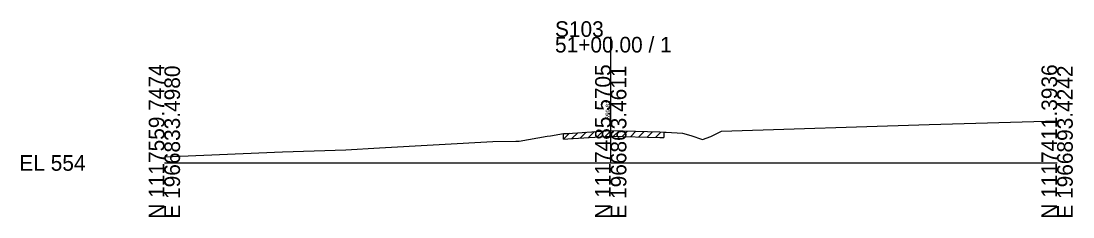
# Model space of a CAD drawing. Extents: x -26 to 163, y -10 to 24018.
# Drawn here: x -25.7 to 162.8, y 490.3 to 525.5 of the extents above; entities that cross this region are included whole.
import ezdxf

# ---------------------------------------------------------------- set-up
doc = ezdxf.new("R2010")
doc.units = 0
for name, color, linetype in [('RD_GPK_XS_Cell', 7, 'Continuous'), ('RD_XS_ExGround', 7, 'Continuous'), ('RD_XS_ExPaveRet', 7, 'Continuous'), ('RD_XS_TX_Elev_EX', 7, 'Continuous')]:
    doc.layers.add(name, color=color, linetype=linetype)

msp = doc.modelspace()

# ---------------------------------------------------------------- linework, layer by layer
at = {"layer": 'RD_GPK_XS_Cell'}
for p, q in [((80, 500), (80, 522.62)), ((0, 500), (80, 500)), ((80, 500), (160, 500))]:
    msp.add_line(p, q, dxfattribs=at)
at = {"layer": 'RD_XS_ExGround'}
msp.add_lwpolyline([(0, 501.08), (21.15, 501.99), (32.51, 502.36), (38.55, 502.7), (58.89, 503.85), (62.97, 503.9), (63.61, 503.91), (68.61, 504.78), (69.19, 504.87), (71.52, 505.26), (72.32, 505.31), (80.02, 505.81), (88.8, 505.56), (89.51, 505.54), (89.92, 505.51), (92.85, 505.32), (94.34, 504.91), (96.47, 504.2), (97.92, 504.77), (99.86, 505.71), (137.06, 506.89), (160, 507.54)], dxfattribs=at)
at = {"layer": 'RD_XS_ExPaveRet'}
for p, q in [((71.52, 504.26), (72.59, 505.33)), ((73.02, 504.36), (74.09, 505.43)), ((74.52, 504.45), (75.59, 505.52)), ((76.02, 504.55), (77.09, 505.62)), ((77.52, 504.65), (78.59, 505.72)), ((79.02, 504.75), (80.09, 505.81)), ((80.52, 504.8), (81.49, 505.77)), ((82.02, 504.75), (82.99, 505.73)), ((83.52, 504.71), (84.49, 505.68)), ((85.02, 504.67), (85.99, 505.64)), ((86.52, 504.62), (87.49, 505.6)), ((88.02, 504.58), (88.99, 505.55)), ((89.51, 505.54), (89.51, 504.54)), ((71.52, 504.26), (71.52, 505.26)), ((71.52, 504.26), (72.32, 504.31)), ((72.32, 504.31), (80.02, 504.81)), ((80.02, 504.81), (88.8, 504.56)), ((88.8, 504.56), (89.51, 504.54))]:
    msp.add_line(p, q, dxfattribs=at)

# ---------------------------------------------------------------- texts
at = {"layer": 'RD_GPK_XS_Cell'}
for s, p in [('S103', (70, 522.62)), ('51+00.00 / 1', (70, 519.82)), ('EL 554', (-26, 498.6))]:
    msp.add_text(s, height=2.8, dxfattribs=at).set_placement(p)
for s, p in [('N 1117559.7474', (0, 490)), ('E 1966833.4980', (2.8, 490)), ('N 1117485.5705', (80, 490)), ('E 1966863.4611', (82.8, 490)), ('N 1117411.3936', (160, 490)), ('E 1966893.4242', (162.8, 490))]:
    msp.add_text(s, height=2.8, rotation=90, dxfattribs=at).set_placement(p)
at = {"layer": 'RD_XS_TX_Elev_EX'}
msp.add_text('559.81', height=0.8, rotation=90, dxfattribs=at).set_placement((79.9, 507.81))

doc.saveas('drawing.dxf')
